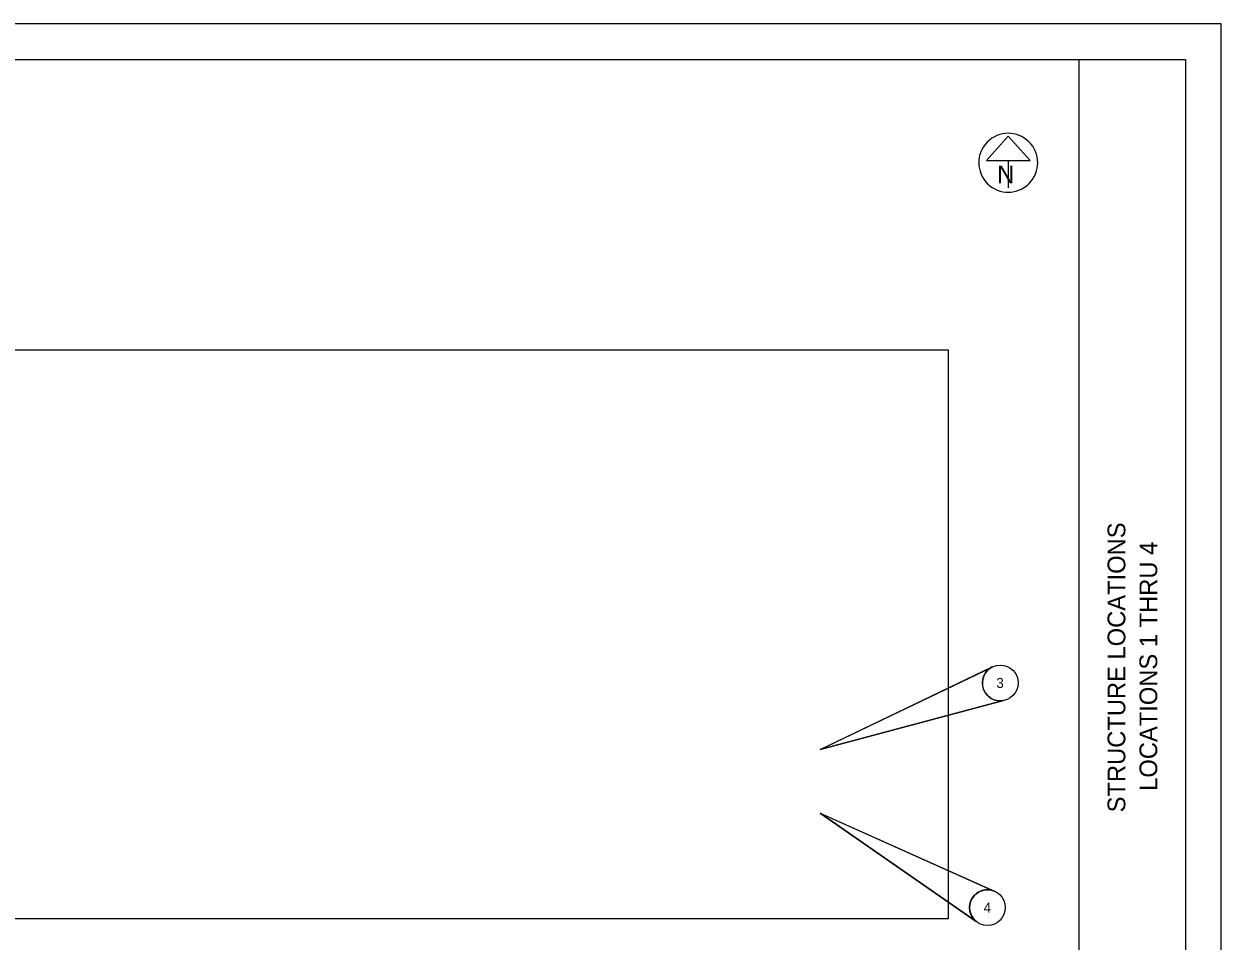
# Model space of a CAD drawing. Extents: x 0 to 1336, y 0 to 440.
# Drawn here: x 342.4 to 680, y 181.5 to 440 of the extents above; entities that cross this region are included whole.
import ezdxf

# ---------------------------------------------------------------- set-up
doc = ezdxf.new("R2010")
doc.units = 0
for name, color, linetype in [('SH_Border', 7, 'Continuous'), ('SH_Cut_Line', 7, 'Continuous'), ('SH_Data', 7, 'Continuous'), ('SN_P_Text', 7, 'Continuous')]:
    doc.layers.add(name, color=color, linetype=linetype)

msp = doc.modelspace()

# ---------------------------------------------------------------- linework, layer by layer
at = {"layer": 'SH_Border'}
msp.add_line((640, 10), (640, 430), dxfattribs=at)
msp.add_lwpolyline([(30, 430), (670, 430), (670, 10), (30, 10)], close=True, dxfattribs=at)
at = {"layer": 'SH_Cut_Line'}
msp.add_lwpolyline([(0, 0), (680, 0), (680, 440), (0, 440)], close=True, dxfattribs=at)
at = {"layer": 'SH_Data'}
for p, q in [((619.98, 408.35), (613.83, 401.52)), ((626.13, 401.52), (619.98, 408.35)), ((613.83, 401.52), (626.13, 401.52)), ((619.98, 401.52), (619.98, 393.79)), ((619.98, 400.87), (619.98, 400.87)), ((619.98, 400.87), (619.98, 400.87))]:
    msp.add_line(p, q, dxfattribs=at)
msp.add_arc((619.98, 400.87), 8.3, 129.7798, 129.7633, dxfattribs=at)
at = {"layer": 'SN_P_Text'}
for p, q in [((566.93, 235.47), (615.62, 258.81)), ((566.93, 235.47), (618.69, 249.28)), ((566.93, 217.47), (610.96, 186.96)), ((566.93, 217.47), (616.23, 195.46))]:
    msp.add_line(p, q, dxfattribs=at)
msp.add_lwpolyline([(67, 348.15), (603, 348.15), (603, 187.73), (67, 187.73)], close=True, dxfattribs=at)
for points in [[(618.69, 249.28), (566.93, 235.47), (566.93, 235.47), (615.47, 258.74)], [(610.96, 186.96), (566.93, 217.47), (566.93, 217.47), (616.08, 195.53)]]:
    msp.add_lwpolyline(points, dxfattribs=at)
for centre in [(617.72, 254.23), (614.11, 190.9)]:
    msp.add_circle(centre, 5.04, dxfattribs=at)
for centre, start, end in [((617.72, 254.23), 116.5302, 281.0526), ((614.11, 190.9), 66.872, 231.3944)]:
    msp.add_arc(centre, 5.04, start, end, dxfattribs=at)

# ---------------------------------------------------------------- texts
at = {"layer": 'SH_Data'}
msp.add_text('N', height=5, dxfattribs=at).set_placement((616.87, 395.05))
for s, p in [('STRUCTURE LOCATIONS', (653, 217.74)), ('LOCATIONS 1 THRU 4', (662, 223.81))]:
    msp.add_text(s, height=5, rotation=90, dxfattribs=at).set_placement(p)
at = {"layer": 'SN_P_Text'}
for s, p in [('3', (616.63, 252.83)), ('4', (613.04, 189.5))]:
    msp.add_text(s, height=2.8, dxfattribs=at).set_placement(p)

doc.saveas('drawing.dxf')
